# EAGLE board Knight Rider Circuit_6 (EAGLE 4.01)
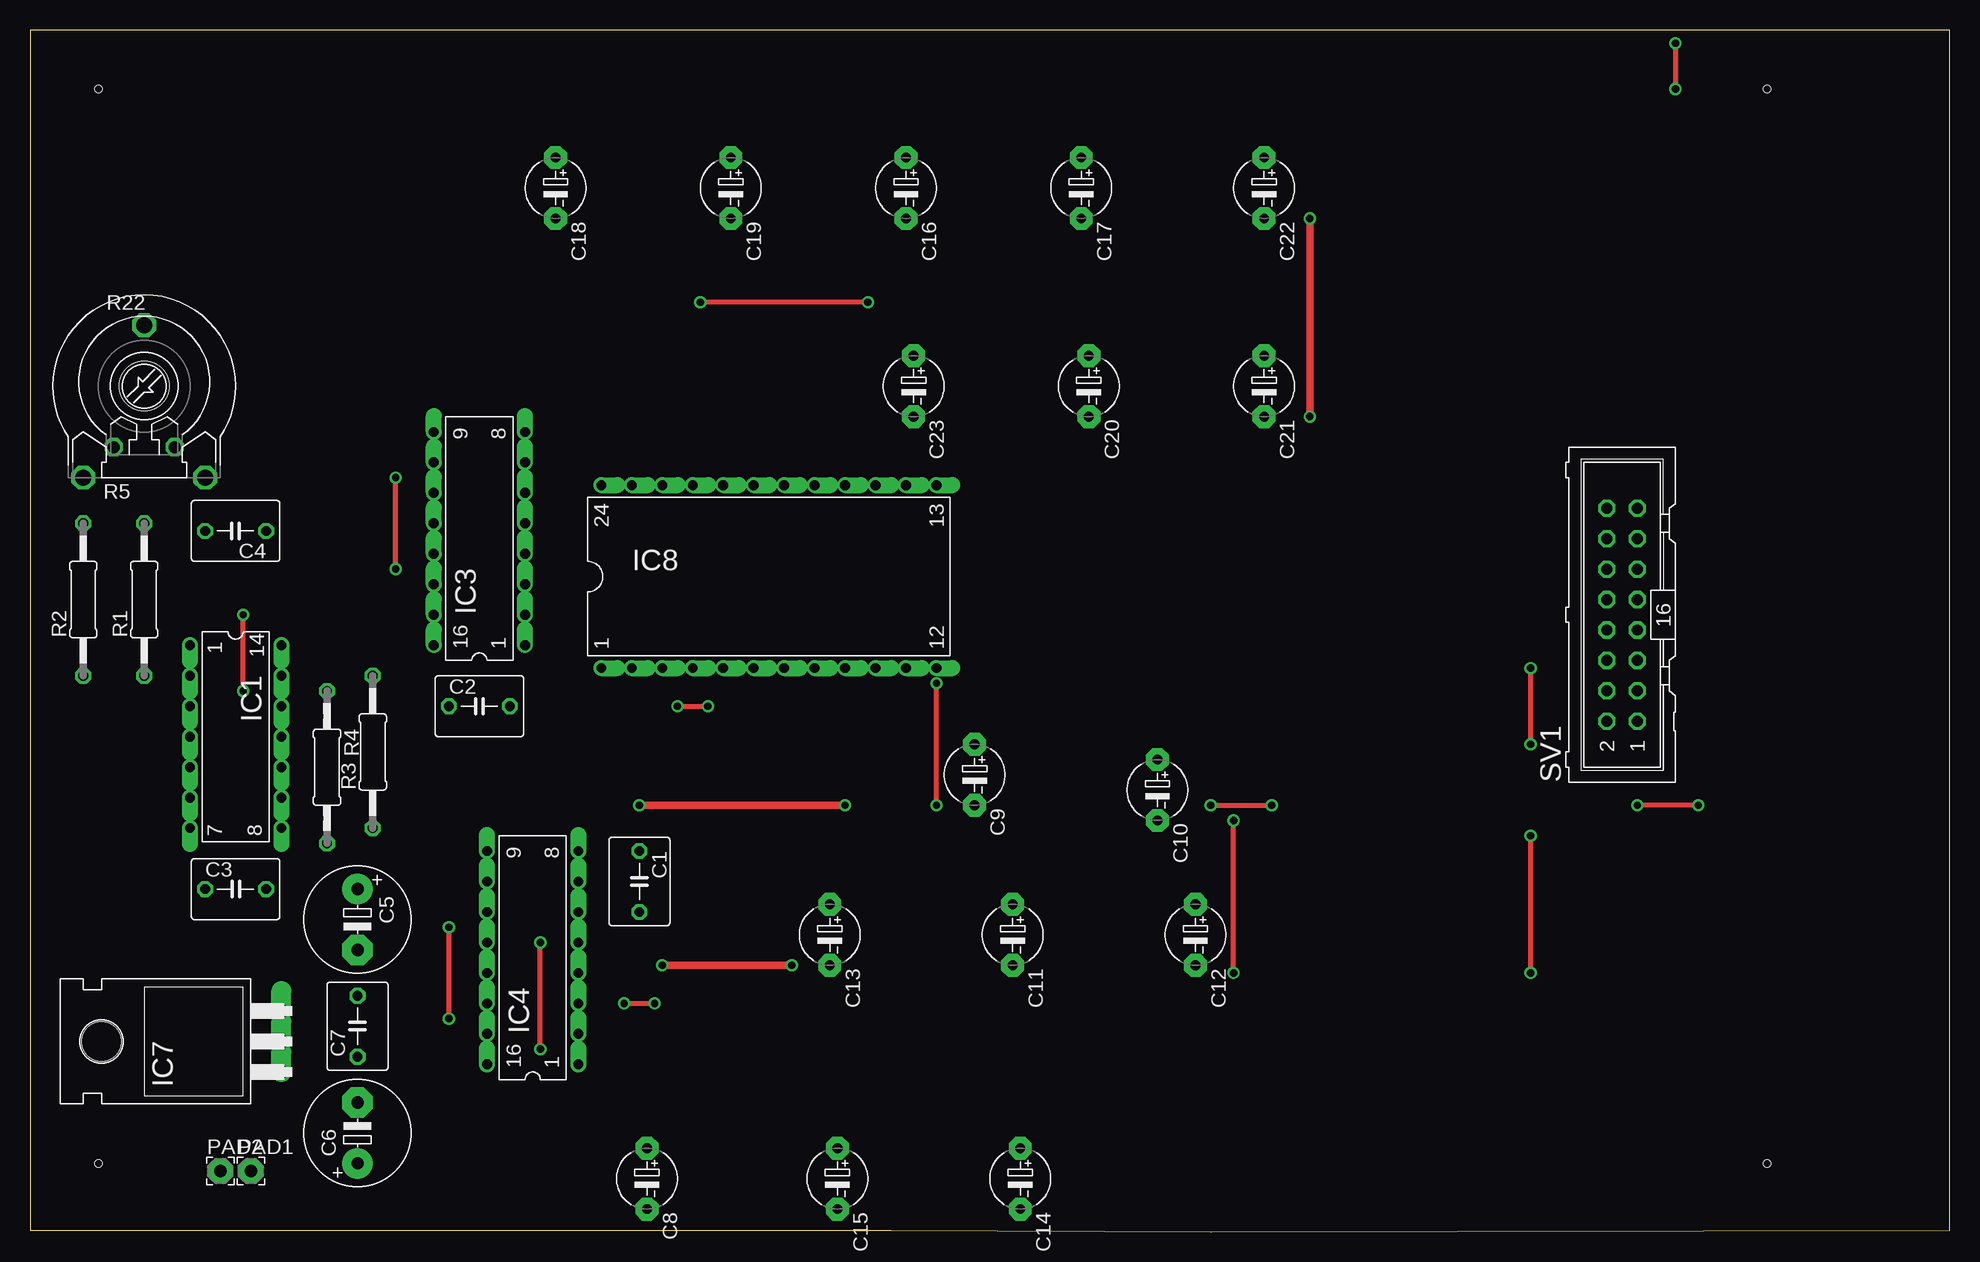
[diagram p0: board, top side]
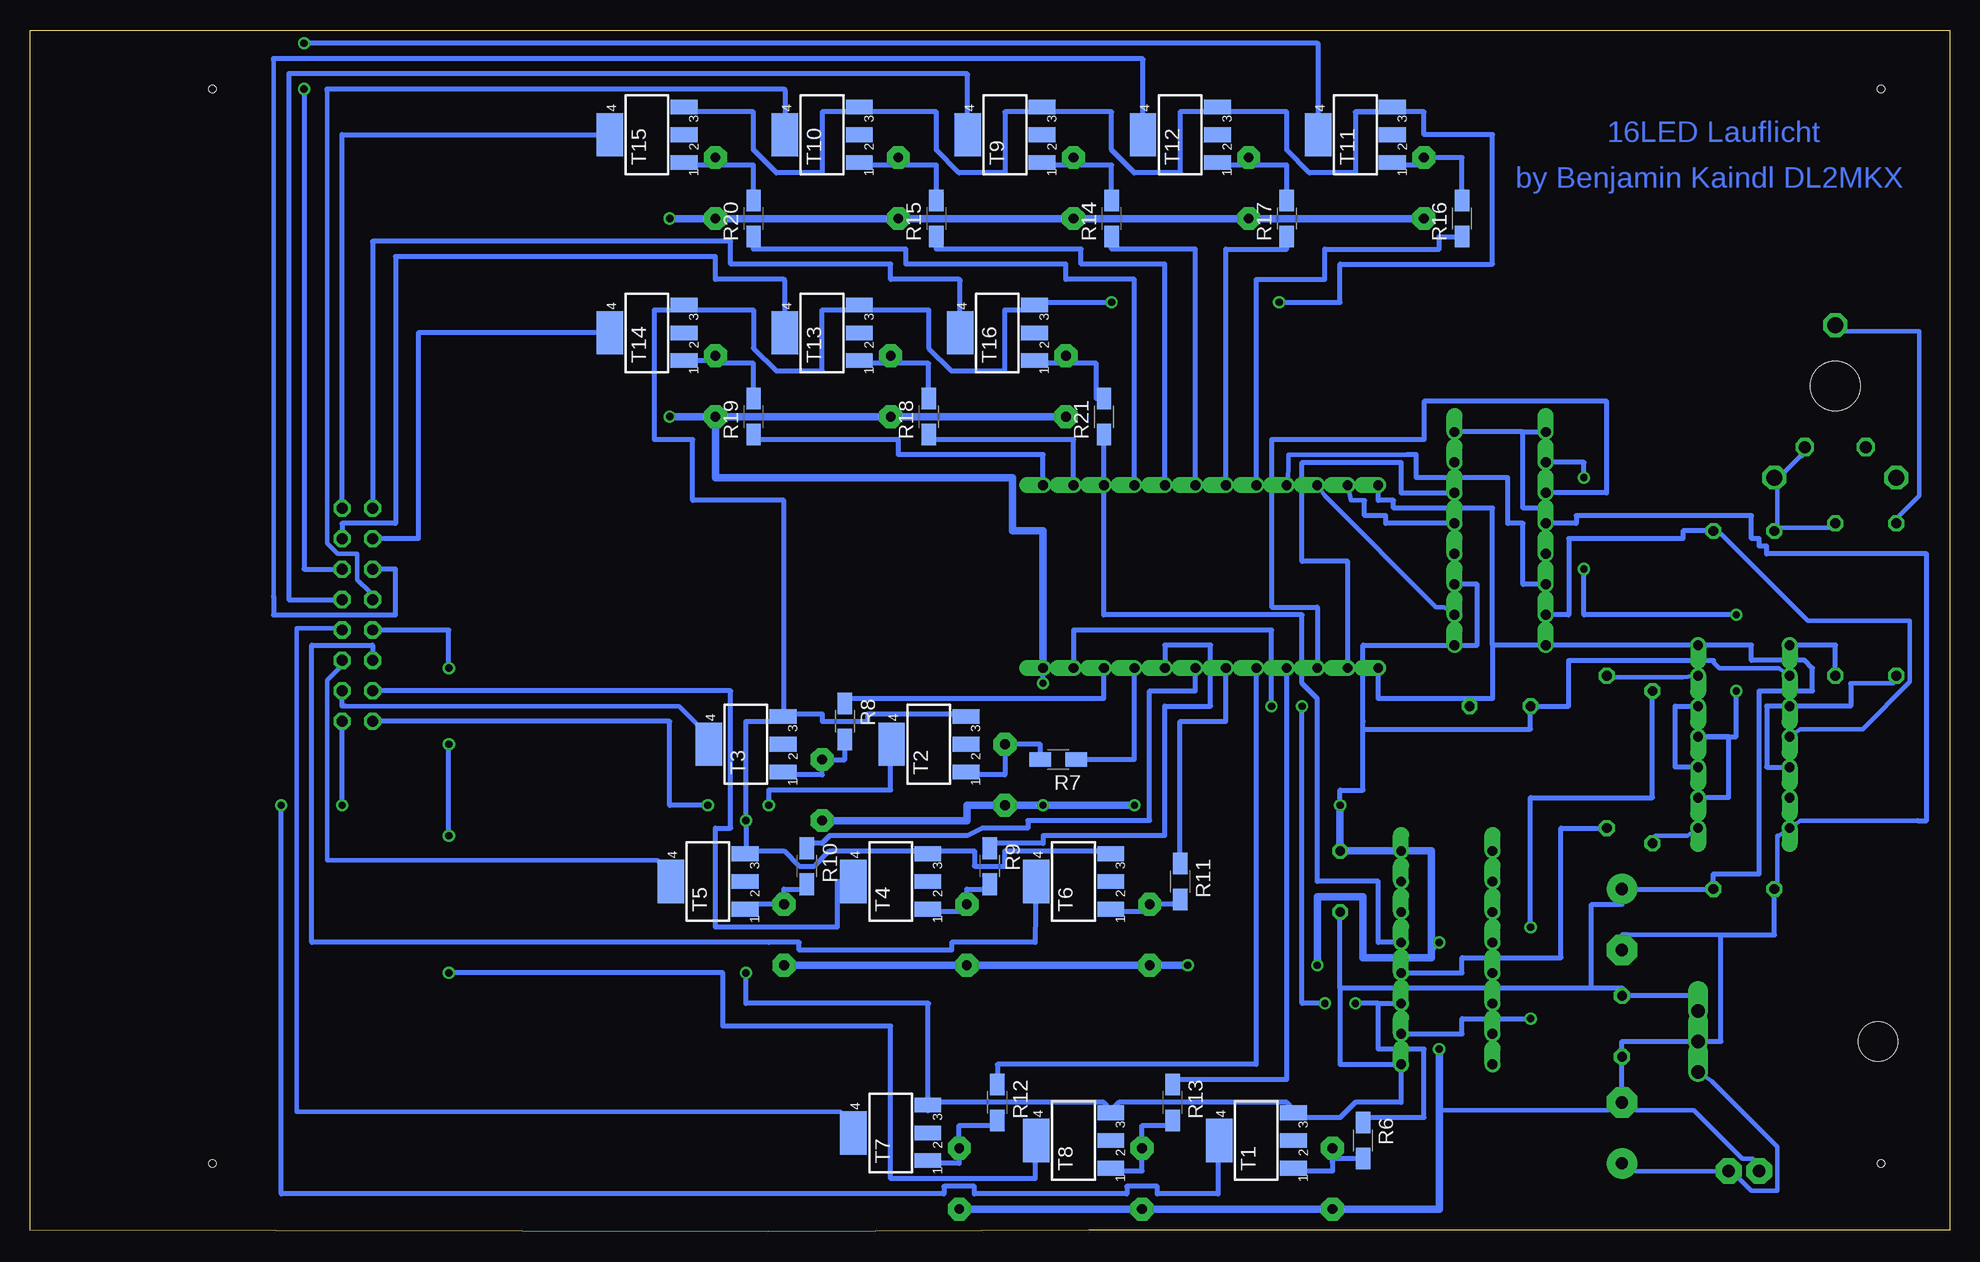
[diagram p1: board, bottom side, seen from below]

Size 160 x 100.17 mm. Coordinates in mm from the lower left corner, seen from the top.
Outline: 0,0.17 71.75,0.17 98.42,0 160,0.17 160,100.17 0,100.17 0,0.17
Copper layers used: Top, Bottom
Holes 0.61 mm at 5.71,5.71 5.71,95.25 144.78,95.25 144.78,5.71

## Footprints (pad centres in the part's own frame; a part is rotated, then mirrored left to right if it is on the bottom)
C050-050X075 = drill 0.813 octagon: 1 -2.54,0; 2 2.54,0
E5-8,5 = drill 1.016 pad 2.54 round: + -2.54,0 | drill 1.016 pad 2.54 octagon: - 2.54,0
E5-5 = drill 0.813 pad 1.905 octagon: + -2.54,0; - 2.54,0
DIL14 = drill 0.813 offset: 1 -7.62,-3.81; 2 -5.08,-3.81; 3 -2.54,-3.81; 4 0,-3.81; 5 2.54,-3.81; 6 5.08,-3.81; 7 7.62,-3.81; 8 7.62,3.81; 9 5.08,3.81; 10 2.54,3.81; 11 0,3.81; 12 -2.54,3.81; 13 -5.08,3.81; 14 -7.62,3.81
DIL16 = drill 0.813 offset: 1 -8.89,-3.81; 2 -6.35,-3.81; 3 -3.81,-3.81; 4 -1.27,-3.81; 5 1.27,-3.81; 6 3.81,-3.81; 7 6.35,-3.81; 8 8.89,-3.81; 9 8.89,3.81; 10 6.35,3.81; 11 3.81,3.81; 12 1.27,3.81; 13 -1.27,3.81; 14 -3.81,3.81; 15 -6.35,3.81; 16 -8.89,3.81
TO220H = drill 1.118 offset: 1 -2.54,-10.16; 2 0,-10.16; 3 2.54,-10.16 | hole 3.302: 0,4.826
DIL24-6 = drill 0.813 offset: 1 -13.97,-7.62; 2 -11.43,-7.62; 3 -8.89,-7.62; 4 -6.35,-7.62; 5 -3.81,-7.62; 6 -1.27,-7.62; 7 1.27,-7.62; 8 3.81,-7.62; 9 6.35,-7.62; 10 8.89,-7.62; 11 11.43,-7.62; 12 13.97,-7.62; 13 13.97,7.62; 14 11.43,7.62; 15 8.89,7.62; 16 6.35,7.62; 17 3.81,7.62; 18 1.27,7.62; 19 -1.27,7.62; 20 -3.81,7.62; 21 -6.35,7.62; 22 -8.89,7.62; 23 -11.43,7.62; 24 -13.97,7.62
2,15/1,0 = drill 1.016 pad 2.159 octagon: 1 0,0
0207/12 = drill 0.813 octagon: 1 -6.35,0; 2 6.35,0
LI15-B = drill 1.321 octagon: 1 -5.08,-7.62; 2 0,5.08; 3 5.08,-7.62 | hole 4.115: 0,0
R1206W = smd 1.8 x 1.2: 1 -1.499,0; 2 1.499,0
PT-10 = drill 1.016 octagon: 1 -2.54,-5.08; 2 2.54,-5.08; 3 0,5.08
ML16 = drill 0.914 octagon: 1 -8.89,-1.27; 2 -8.89,1.27; 3 -6.35,-1.27; 4 -6.35,1.27; 5 -3.81,-1.27; 6 -3.81,1.27; 7 -1.27,-1.27; 8 -1.27,1.27; 9 1.27,-1.27; 10 1.27,1.27; 11 3.81,-1.27; 12 3.81,1.27; 13 6.35,-1.27; 14 6.35,1.27; 15 8.89,-1.27; 16 8.89,1.27
SOT223 = smd 1.219 x 2.235: 1 -2.311,-3.099; 2 0,-3.099; 3 2.311,-3.099 | smd 3.6 x 2.2: 4 0,3.099

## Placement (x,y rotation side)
C1  100nF  [C050-050X075]  50.8,29.21 270 top
C2  100nF  [C050-050X075]  37.46,43.81 0 top
C3  100nF  [C050-050X075]  17.14,28.58 0 top
C4  100n  [C050-050X075]  17.14,58.42 180 top
C5  100µF  [E5-8,5]  27.3,26.04 270 top
C6  220µF  [E5-8,5]  27.3,8.26 90 top
C7  100nF  [C050-050X075]  27.3,17.15 90 top
C8  100µF  [E5-5]  51.43,4.45 270 top
C9  100µF  [E5-5]  78.73,38.1 270 top
C10  100µF  [E5-5]  93.97,36.83 270 top
C11  100µF  [E5-5]  81.91,24.77 270 top
C12  100µF  [E5-5]  97.15,24.77 270 top
C13  100µF  [E5-5]  66.67,24.77 270 top
C14  100µF  [E5-5]  82.55,4.45 270 top
C15  100µF  [E5-5]  67.3,4.45 270 top
C16  100µF  [E5-5]  73.02,87 270 top
C17  100µF  [E5-5]  87.62,87 270 top
C18  100µF  [E5-5]  43.81,87 270 top
C19  100µF  [E5-5]  58.41,87 270 top
C20  100µF  [E5-5]  88.26,70.48 270 top
C21  100µF  [E5-5]  102.86,70.48 270 top
C22  100µF  [E5-5]  102.86,87 270 top
C23  100µF  [E5-5]  73.66,70.48 270 top
IC1  4001N  [DIL14]  17.14,41.27 270 top
IC3  4516N  [DIL16]  37.46,57.78 90 top
IC4  4049N  [DIL16]  41.91,22.86 90 top
IC7  7812  [TO220H]  10.79,15.88 90 top
IC8  4515N  [DIL24-6]  61.59,54.61 0 top
PAD1  [2,15/1,0]  18.41,5.08 0 top
PAD2  [2,15/1,0]  15.87,5.08 0 top
R1  47k  [0207/12]  9.52,52.7 90 top
R2  100k  [0207/12]  4.44,52.7 90 top
R3  47k  [0207/12]  28.57,40 90 top
R4  47k  [0207/12]  24.76,38.73 270 top
R5  470k  [LI15-B]  9.52,70.48 0 top
R6  1k2  [R1206W]  48.89,7.62 270 bottom
R7  1k2  [R1206W]  74.29,39.37 180 bottom
R8  1k2  [R1206W]  92.07,42.54 270 bottom
R9  1k2  [R1206W]  80,30.48 270 bottom
R10  1k2  [R1206W]  95.24,30.48 270 bottom
R11  1k2  [R1206W]  64.13,29.21 270 bottom
R12  1k2  [R1206W]  79.37,10.79 270 bottom
R13  1k2  [R1206W]  64.77,10.79 270 bottom
R14  1k2  [R1206W]  69.84,84.45 90 bottom
R15  1k2  [R1206W]  84.45,84.45 90 bottom
R16  1k2  [R1206W]  40.64,84.45 90 bottom
R17  1k2  [R1206W]  55.24,84.45 90 bottom
R18  1k2  [R1206W]  85.08,67.95 90 bottom
R19  1k2  [R1206W]  99.69,67.95 90 bottom
R20  1k2  [R1206W]  99.69,84.45 90 bottom
R21  1k2  [R1206W]  70.48,67.95 90 bottom
R22  [PT-10]  9.52,70.48 0 top
SV1  [ML16]  132.71,51.43 90 top
T1  BCP53-16  [SOT223]  57.78,7.62 90 bottom
T2  BCP53-16  [SOT223]  85.08,40.64 90 bottom
T3  BCP53-16  [SOT223]  100.32,40.64 90 bottom
T4  BCP53-16  [SOT223]  88.26,29.21 90 bottom
T5  BCP53-16  [SOT223]  103.5,29.21 90 bottom
T6  BCP53-16  [SOT223]  73.02,29.21 90 bottom
T7  BCP53-16  [SOT223]  88.26,8.26 90 bottom
T8  BCP53-16  [SOT223]  73.02,7.62 90 bottom
T9  BCP53-16  [SOT223]  78.73,91.44 90 bottom
T10  BCP53-16  [SOT223]  93.97,91.44 90 bottom
T11  BCP53-16  [SOT223]  49.53,91.44 90 bottom
T12  BCP53-16  [SOT223]  64.13,91.44 90 bottom
T13  BCP53-16  [SOT223]  93.97,74.93 90 bottom
T14  BCP53-16  [SOT223]  108.58,74.93 90 bottom
T15  BCP53-16  [SOT223]  108.58,91.44 90 bottom
T16  BCP53-16  [SOT223]  79.37,74.93 90 bottom

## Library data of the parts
C1-C23 R1-R4 R6-R21 = rcl
IC1 IC4 = 40xx
IC3 IC8 = 45xx
IC7 = linear
PAD1 PAD2 = wirepad
R5 R22 = pot
SV1 = con-ml
T1-T16 = zetex

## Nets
N$1: IC1.1 R1.1
N$2: IC1.3 IC1.5 IC1.6 R2.1
N$3: C21.+ R19.2 T14.1
N$4: C4.2 R1.2 R5.3 R22.2
N$5: IC4.4 R3.1
N$6: C6.+ IC7.1 PAD1.1
N$7: IC4.2 R4.1
N$8: C1.2 C2.2 C3.2 C5.+ C7.2 IC1.14 IC3.16 IC4.1 IC7.3 IC8.1 IC8.24 T1.3 T2.3 T3.3 T4.3 T5.3 T6.3 T7.3 T8.3 T9.3 T10.3 T11.3 T12.3 T13.3 T14.3 T15.3 T16.3
N$9: IC1.9 IC1.11 IC3.10
N$10: IC1.8 R4.2
N$11: IC1.13 R3.2
N$12: IC1.10 IC1.12
N$13: C22.+ R20.2 T15.1
N$14: C4.1 IC1.4 IC3.15
N$15: C1.1 C2.1 C3.1 C5.- C6.- C7.1 C8.- C9.- C10.- C11.- C12.- C13.- C14.- C15.- C16.- C17.- C18.- C19.- C20.- C21.- C22.- C23.- IC1.2 IC1.7 IC3.1 IC3.3 IC3.4 IC3.5 IC3.8 IC3.9 IC3.12 IC3.13 IC4.8 IC7.2 IC8.12 IC8.23 PAD2.1
N$16: SV1.15 T15.4
N$17: SV1.16 T16.4
N$18: C23.+ R21.2 T16.1
N$20: IC4.3 IC8.11 R6.1
N$21: R2.2 R5.2 R22.3
N$22: IC3.6 IC8.2
N$23: IC3.11 IC8.3
N$24: IC3.14 IC8.21
N$25: IC3.2 IC8.22
N$28: IC8.9 R7.1
N$29: IC8.10 R8.1
N$30: IC8.8 R9.1
N$31: IC8.7 R10.1
N$32: IC8.6 R11.1
N$33: IC4.5 IC8.15 R21.1
N$34: IC8.16 R20.1
N$35: IC8.13 R19.1
N$36: IC8.14 R18.1
N$37: IC8.19 R17.1
N$38: IC8.20 R16.1
N$39: IC8.17 R15.1
N$40: IC8.18 R14.1
N$41: IC8.4 R13.1
N$42: IC8.5 R12.1
N$44: C18.+ R16.2 T11.1
N$45: SV1.1 T1.4
N$46: SV1.14 T14.4
N$47: SV1.13 T13.4
N$49: C20.+ R18.2 T13.1
N$52: C19.+ R17.2 T12.1
N$53: SV1.12 T12.4
N$57: SV1.7 T7.4
N$59: C17.+ R15.2 T10.1
N$60: SV1.10 T10.4
N$62: SV1.9 T9.4
N$64: C16.+ R14.2 T9.1
N$66: SV1.8 T8.4
N$68: C15.+ R13.2 T8.1
N$71: C14.+ R12.2 T7.1
N$74: SV1.6 T6.4
N$76: C13.+ R11.2 T6.1
N$79: C12.+ R10.2 T5.1
N$80: SV1.5 T5.4
N$82: SV1.4 T4.4
N$84: C11.+ R9.2 T4.1
N$86: SV1.3 T3.4
N$88: C10.+ R8.2 T3.1
N$91: C9.+ R7.2 T2.1
N$92: SV1.2 T2.4
N$95: C8.+ R6.2 T1.1
N$112: SV1.11 T11.4

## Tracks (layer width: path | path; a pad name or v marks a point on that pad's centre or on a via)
N$1
  Bottom 0.406: R1.1 9.52,48.89 IC1.1
N$2
  Bottom 0.381: 8.25,45.72 4.69,45.72 R2.1
  Bottom 0.406: 8.25,45.72 8.25,43.81 IC1.3 15.24,43.81 15.24,38.73 IC1.5 IC1.6
N$3
  Bottom 0.406: T14.1 103.27,72.62 C21.+ 102.86,72.39 99.69,72.39 R19.2
N$4
  Bottom 0.381: R1.2 10.03,58.67 13.97,58.67 C4.2 14.35,59.05 14.35,61.98 R5.3 13.71,63.37 12.44,64.64 12.31,64.64 R22.2
N$5
  Bottom 0.406: IC4.4 40.64,21.59 40.64,22.86 32.38,22.86 32.38,33.66 R3.1
N$6
  Bottom 0.381: IC7.1 19.81,12.57 14.35,7.11 14.35,3.43 16.5,3.43 17.52,4.45 PAD1.1 26.16,5.08 C6.+
N$7  (via drill 0.61)
  Top 0.406: v34.92,17.78 v34.92,25.4
  Bottom 0.406: IC4.2 40.64,16.51 40.64,17.78 v34.92,17.78 | v34.92,25.4 34.92,36.2 24.76,36.2 R4.1
N$8  (via drill 0.61 pad 1.02)
  Top 0.406: v100.32,21.59 v100.32,34.29 | v69.84,77.47 v55.88,77.47 v69.84,77.47
  Bottom 0.406: 54.61,9.93 54.61,10.16 | 54.61,9.93 T1.3 54.68,10.24 55.24,10.79 69.21,10.79 69.92,10.08 T8.3 69.92,10.24 70.48,10.79 84.45,10.79 85.16,10.08 T7.3 85.16,18.97 85.08,19.05 100.32,19.05 v100.32,21.59 | 54.61,9.93 54.61,9.53 50.8,9.53 49.53,10.79 45.72,10.79 IC4.1 50.8,13.97 50.8,20.32 | T6.3 69.92,31.83 69.84,31.75 78.73,31.75 78.73,30.48 81.27,30.48 81.27,31.75 85.08,31.75 | 90.16,43.18 81.99,43.18 T2.3 81.99,43.1 81.91,43.18 90.16,43.18 | T3.3 97.23,43.18 97.15,43.18 | 49.53,93.34 46.43,93.34 T11.3 46.43,93.42 46.35,93.34 | 55.24,93.34 60.96,93.34 | T12.3 61.03,93.42 60.96,93.34 | 60.96,93.34 64.13,93.34 | 69.84,93.34 75.56,93.34 | T9.3 75.64,93.42 75.56,93.34 | 75.56,93.34 78.73,93.34 | T10.3 90.88,93.42 90.8,93.34 | 90.8,93.34 84.45,93.34 84.45,90.17 82.55,88.27 78.73,88.27 78.73,93.34 | 69.84,93.34 78.73,93.34 | 69.84,93.34 69.84,90.17 67.94,88.27 64.13,88.27 64.13,93.34 | 55.24,93.34 64.13,93.34 | 55.24,93.34 55.24,90.17 53.34,88.27 49.53,88.27 49.53,93.34 | 46.35,93.34 49.53,93.34 | T15.3 105.48,93.42 105.41,93.34 99.69,93.34 99.69,90.17 97.78,88.27 93.97,88.27 93.97,93.34 91.44,93.34 | 90.8,93.34 91.44,93.34 | 90.8,93.34 90.8,93.98 91.44,93.34 | 90.8,76.84 90.88,76.91 T13.3 | T14.3 105.48,76.91 105.41,76.84 | 90.16,43.18 90.16,42.54 93.97,42.54 93.97,43.18 97.15,43.18 | 97.15,42.54 97.15,43.18 | T5.3 100.4,31.67 100.32,31.75 | 97.15,42.54 97.23,42.62 T3.3 | 97.15,42.54 100.32,42.54 v100.32,34.29 100.32,31.75 | 100.32,31.75 97.15,31.75 95.88,30.48 94.61,30.48 93.34,31.75 85.08,31.75 | 85.08,31.75 85.16,31.67 T4.3 | T16.3 76.27,77.39 76.19,77.47 | 46.35,93.34 43.81,93.34 43.81,91.44 38.1,91.44 38.1,80.65 50.8,80.65 50.8,77.47 v55.88,77.47
  Bottom 0.406: 76.19,77.47 v69.84,77.47 | 76.19,77.47 76.19,76.84 78.73,76.84 78.73,71.76 83.18,71.76 85.08,73.66 85.08,76.84 90.8,76.84 | 90.8,76.84 93.97,76.84 93.97,71.76 97.78,71.76 99.69,73.66 99.69,76.84 105.41,76.84 | 105.41,76.84 107.94,76.84 107.94,66.04 104.77,66.04 104.77,60.96 97.15,60.96 97.15,43.18 | 97.15,43.18 97.23,43.1 T3.3 | 27.3,20.32 29.84,20.32 29.84,27.31 27.3,27.31 C5.+ C3.2 19.68,29.85 15.87,29.85 15.87,45.09 11.43,45.09 11.43,46.99 12.06,47.62 16.5,47.62 16.5,48.89 IC1.14 IC3.16 38.1,48.89 | IC7.3 20.95,19.69 C7.2 27.3,20.32 | 50.8,20.32 C1.2 | 27.3,20.32 50.8,20.32 | IC8.24 47.62,60.96 46.35,60.96 46.35,60.32 38.1,60.32 38.1,48.89 | 38.1,48.89 38.1,44.45 40,44.45 | 40,44.45 C2.2 | 40,44.45 47.62,44.45 IC8.1
N$9  (via drill 0.61)
  Top 0.406: v30.47,55.24 v30.47,62.86 | v17.77,45.09 v17.77,51.43
  Bottom 0.406: IC1.9 18.41,36.2 18.41,41.27 IC1.11 17.77,41.27 v17.77,45.09 | IC3.10 30.47,64.14 v30.47,62.86 | v30.47,55.24 30.47,51.43 v17.77,51.43
N$10
  Bottom 0.381: IC1.8 21.84,33.02 24.51,33.02 R4.2
N$11
  Bottom 0.381: IC1.13 22.22,46.23 27.93,46.23 R3.2
N$12
  Bottom 0.406: IC1.10 22.86,38.73 22.86,43.81 IC1.12
N$13
  Bottom 0.406: R20.2 99.69,88.9 102.86,88.9 | 102.86,88.9 C22.+ | T15.1 105.48,88.98 105.41,88.9 102.86,88.9
N$14
  Bottom 0.381: IC1.4 12.44,41.91 7.23,41.91 3.3,45.85 3.3,50.93 11.81,50.93 19.04,58.17 C4.1
  Bottom 0.406: IC3.15 31.74,51.43 31.74,57.78 22.22,57.78 22.22,58.42 C4.1
N$15  (via drill 0.61 pad 1.02)
  Top 0.406: v75.56,35.56 v75.56,45.72 | v52.7,22.23 v63.5,22.23 | v50.8,35.56 v67.94,35.56 | v42.54,15.24 v42.54,24.13
  Top 0.61: v52.7,22.23 v63.5,22.23 | v52.7,22.23 v63.5,22.23 | v52.7,22.23 v63.5,22.23 | v52.7,22.23 v63.5,22.23 | v52.7,22.23 v63.5,22.23 | v50.8,35.56 v67.94,35.56 | v106.67,67.95 v106.67,84.45
  Bottom 0.381: 19.68,47.5 19.17,46.99 14.22,46.99 IC1.2 | 48.76,60.96 49.91,60.96 IC8.23 | PAD2.1 16.38,6.1 17.27,6.1 21.33,10.16 26.16,10.16 C6.- 28.44,10.16 42.54,10.16 | C3.1 14.35,29.21 14.35,33.02 14.22,33.02 IC1.7 12.44,34.29 2.66,34.29 | 19.04,24.77 26.79,24.77
  Bottom 0.406: C8.- C15.- C14.- | v75.56,45.72 IC8.12 | C12.- C11.- C13.- v63.5,22.23 | C1.1 v50.8,35.56 50.8,36.83 48.89,36.83 48.89,41.91 | v67.94,35.56 C9.- | 43.18,24.13 v42.54,24.13 43.18,23.5 43.18,22.86 | C3.1 14.6,24.77 19.04,24.77 19.04,15.88 IC7.2 27.3,15.88 C7.1 C6.- | 26.79,24.77 27.3,24.77 C5.- | 2.66,34.29 1.9,34.29 1.9,56.52 15.24,56.52 15.24,57.15 15.87,57.15 15.87,57.78 16.5,57.78 16.5,59.69 31.11,59.69 31.11,59.05 IC3.12 | 19.68,47.5 19.68,47.62 31.74,47.62 31.74,43.81 C2.1 34.92,41.91 48.89,41.91 | 48.89,41.91 48.89,42.54 48.89,48.89 IC3.1 39.37,48.89 39.37,53.98 IC3.3 IC3.4 IC3.5 46.98,59.05 46.98,59.69 48.76,59.69 48.76,60.96 | 35.55,66.68 IC3.9 | 35.55,66.68 IC3.8 | 35.55,66.68 35.55,60.32 33.65,60.32 IC3.12 | IC3.12 IC3.13
  Bottom 0.61: C14.- C15.- C8.- | C8.- C14.- | C1.1 IC4.8 43.18,31.75 | v63.5,22.23 C13.- | C13.- C11.- | C11.- C12.- | C8.- C14.- | C8.- 42.54,1.91 42.54,10.16 v42.54,15.24 | C10.- 81.91,34.29 81.91,35.56 C9.- | v75.56,35.56 C9.- | C1.1 v50.8,35.56 C1.1 | v63.5,22.23 C13.- | C13.- C11.- | C13.- C11.- | v63.5,22.23 C13.- | v63.5,22.23 C13.- | v63.5,22.23 C13.- | v52.7,22.23 52.7,27.94 48.89,27.94 48.89,22.86 43.18,22.86 43.18,24.13 43.18,31.75 | 43.18,31.75 C1.1 | v67.94,35.56 v75.56,35.56 | v75.56,35.56 C9.- | C18.- C19.- C16.- C17.- C22.- v106.67,84.45 | C21.- C20.- C23.- | C21.- v106.67,67.95 | IC8.12 75.56,58.42 78.1,58.42 78.1,62.86 102.86,62.86 C21.-
N$16
  Bottom 0.406: T15.4 133.98,91.44 SV1.15
N$17
  Bottom 0.406: T16.4 82.47,79.3 82.55,79.38 88.26,79.38 88.26,80.65 101.59,80.65 101.59,82.55 131.44,82.55 SV1.16
N$18
  Bottom 0.406: R21.2 71.11,69.44 71.11,72.39 73.66,72.39 | 73.66,72.39 C23.+ | T16.1 76.19,72.62 76.19,72.39 73.66,72.39
N$20  (via drill 0.61 pad 1.02)
  Top 0.406: v49.53,19.05 v52.07,19.05 | v53.97,43.81 v56.51,43.81
  Bottom 0.406: R6.1 48.89,9.53 43.81,9.53 43.81,15.24 47.62,15.24 47.62,19.05 | 47.62,19.05 IC4.3 | 47.62,19.05 v49.53,19.05 | v52.07,19.05 53.97,19.05 v53.97,43.81 | v56.51,43.81 56.51,50.16 73.02,50.16 IC8.11
N$21
  Bottom 0.381: R2.2 4.19,59.69 2.54,61.34 2.54,75.06 8.63,75.06 R5.2 9.27,74.8
N$22
  Bottom 0.406: IC8.2 50.16,55.88 53.97,55.88 53.97,64.14 45.72,64.14 45.72,61.59 IC3.6
N$23
  Bottom 0.406: IC3.11 28.57,61.59 28.57,69.22 43.81,69.22 43.81,66.04 56.51,66.04 56.51,52.07 52.7,52.07 IC8.3
N$24
  Bottom 0.381: 45.21,64.77 55.11,64.77 55.11,63.5 IC8.21
  Bottom 0.406: IC3.14 35.55,53.98 35.55,59.05 36.83,59.05 36.83,62.86 44.45,62.86 44.45,64.77 45.21,64.77
N$25
  Bottom 0.381: IC3.2 42.16,52.07 42.79,52.07 52.07,61.34 IC8.22
N$28
  Bottom 0.406: R7.1 67.94,39.37 IC8.9
N$29
  Bottom 0.406: R8.1 92.07,44.45 70.48,44.45 IC8.10
N$30
  Bottom 0.406: R9.1 80,32.38 75.56,32.38 75.56,33.02 65.4,33.02 65.4,43.81 61.59,43.81 61.59,48.89 65.4,48.89 IC8.8
N$31
  Bottom 0.406: R10.1 95.24,32.38 93.97,32.38 93.34,33.02 81.91,33.02 80.64,33.66 76.83,33.66 76.83,34.29 66.67,34.29 66.67,45.09 62.86,45.09 IC8.7
N$32
  Bottom 0.406: R11.1 64.13,42.54 60.32,42.54 IC8.6
N$33
  Bottom 0.406: IC4.5 47.62,24.13 47.62,29.21 52.7,29.21 52.7,44.45 53.97,45.72 53.97,51.43 70.48,51.43 IC8.15 R21.1
N$34
  Bottom 0.406: R20.1 99.69,81.92 86.99,81.92 86.99,80.65 73.66,80.65 73.66,79.38 67.94,79.38 IC8.16
N$35
  Bottom 0.406: R19.1 99.69,66.04 87.62,66.04 87.62,64.77 75.56,64.77 IC8.13
N$36
  Bottom 0.406: R18.1 85.08,66.04 73.02,66.04 IC8.14
N$37
  Bottom 0.406: R17.1 55.24,81.92 60.32,81.92 IC8.19
N$38
  Bottom 0.406: R16.1 42.54,82.96 42.54,81.92 52.07,81.92 52.07,79.38 57.78,79.38 IC8.20
N$39
  Bottom 0.406: R15.1 84.45,81.92 72.38,81.92 72.38,80.65 65.4,80.65 IC8.17
N$40
  Bottom 0.406: R14.1 69.84,81.92 62.86,81.92 IC8.18
N$41
  Bottom 0.406: R13.1 64.77,12.7 55.24,12.7 IC8.4
N$42
  Bottom 0.406: R12.1 79.37,13.97 57.78,13.97 IC8.5
N$44
  Bottom 0.406: R16.2 40.64,89.54 C18.+ 43.81,88.9 46.43,88.9 T11.1
N$45  (via drill 0.61)
  Top 0.406: v139.06,35.56 v133.98,35.56
  Bottom 0.406: T1.4 60.96,7.62 60.96,3.17 66.03,3.17 66.03,3.81 68.57,3.81 68.57,3.17 81.27,3.17 81.27,3.81 83.81,3.81 83.81,3.17 139.06,3.17 v139.06,35.56 | v133.98,35.56 SV1.1
N$46
  Bottom 0.406: T14.4 127.63,74.93 127.63,57.78 SV1.14
N$47
  Bottom 0.406: T13.4 97.07,79.3 97.15,79.38 102.86,79.38 102.86,81.28 111.5,81.28 129.53,81.28 129.53,59.05 133.98,59.05 SV1.13
N$49
  Bottom 0.406: R18.2 85.08,72.39 88.26,72.39 | 88.26,72.39 C20.+ | T13.1 90.88,72.47 90.8,72.39 88.26,72.39
N$52
  Bottom 0.406: R17.2 55.24,88.9 58.41,88.9 | 58.41,88.9 C19.+ | T12.1 61.03,88.9 58.41,88.9
N$53
  Bottom 0.381: 139.69,97.66 139.69,52.96
  Bottom 0.406: T12.4 67.23,97.71 67.3,97.79 139.69,97.79 139.69,97.66 | 139.69,52.96 139.69,51.43 129.53,51.43 129.53,55.24 SV1.12
N$57
  Bottom 0.381: SV1.7 134.36,50.29 137.79,50.29 137.79,10.03 92.45,10.03 T7.4
N$59
  Bottom 0.406: R15.2 84.45,88.9 87.62,88.9 | 87.62,88.9 C17.+ | T10.1 90.88,88.98 90.8,88.9 87.62,88.9
N$60
  Bottom 0.381: 135.25,95.12 135.25,57.4 134.36,56.52 132.71,56.52 132.71,54.36 131.69,53.34 SV1.10
  Bottom 0.406: T10.4 97.07,95.17 97.15,95.25 135.25,95.25 135.25,95.12
N$62
  Bottom 0.406: T9.4 81.83,96.44 81.91,96.52 138.42,96.52 138.42,52.7 SV1.9
N$64
  Bottom 0.406: R14.2 69.84,88.9 72.38,88.9 C16.+ 73.02,88.9 75.56,88.9 75.64,88.98 T9.1
N$66  (via drill 0.61)
  Top 0.406: v125.09,40.64 v125.09,46.99 | v125.09,21.59 v125.09,33.02
  Bottom 0.406: T8.4 76.19,7.62 76.19,4.45 88.26,4.45 88.26,17.15 102.23,17.15 102.23,21.59 v125.09,21.59 | SV1.8 125.09,50.16 v125.09,46.99 | v125.09,33.02 v125.09,40.64
N$68
  Bottom 0.406: T8.1 69.84,5.31 69.84,5.08 67.3,5.08 C15.+ 67.3,8.89 64.77,8.89 R13.2
N$71
  Bottom 0.406: R12.2 79.37,8.89 82.55,8.89 C14.+ 82.55,5.71 85.08,5.71 85.16,5.79 T7.1
N$74
  Bottom 0.406: T6.4 76.19,24.13 83.18,24.13 83.18,23.5 95.88,23.5 95.88,24.13 98.42,24.13 136.52,24.13 136.52,48.89 131.44,48.89 SV1.6
N$76
  Bottom 0.406: R11.2 64.13,27.31 C13.+ 66.67,26.67 69.84,26.67 69.92,26.75 T6.1
N$79
  Bottom 0.406: R10.2 95.24,28.58 97.15,28.58 C12.+ 100.32,27.31 100.32,26.67 100.4,26.75 T5.1
N$80
  Bottom 0.381: SV1.5 134.23,46.99 135.25,45.97 135.25,30.99 107.69,30.99 T5.4
N$82
  Bottom 0.406: T4.4 92.7,29.21 92.7,25.4 102.86,25.4 102.86,33.66 101.59,33.66 101.59,45.09 SV1.4
N$84
  Bottom 0.406: R9.2 80,28.58 81.91,28.58 C11.+ 81.91,26.67 85.08,26.67 85.16,26.75 T4.1
N$86
  Bottom 0.381: 133.73,43.81 105.91,43.81 104.52,42.42 T3.4
  Bottom 0.406: 133.73,43.81 133.98,43.81 SV1.3
N$88
  Bottom 0.406: R8.2 92.07,39.37 C10.+ 93.97,38.1 97.23,38.1 T3.1
N$91
  Bottom 0.406: R7.2 75.79,40.64 C9.+ 78.73,38.1 81.99,38.1 T2.1
N$92  (via drill 0.61)
  Top 0.406: v98.42,35.56 v103.5,35.56
  Bottom 0.406: T2.4 88.26,40.64 88.26,36.83 98.42,36.83 v98.42,35.56 | v103.5,35.56 106.67,35.56 106.67,42.54 SV1.2
N$95
  Bottom 0.406: 51.43,5.71 51.43,5.08 54.61,5.08 T1.1 | 51.43,5.71 C8.+ | R6.2 51.43,6.12 51.43,5.71
N$112  (via drill 0.61)
  Top 0.406: v137.16,99.06 v137.16,95.25
  Bottom 0.406: T11.4 52.62,98.98 52.7,99.06 v137.16,99.06 | SV1.11 137.16,55.24 v137.16,95.25

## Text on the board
Bottom: 16LED Lauflicht | by Benjamin Kaindl DL2MKX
